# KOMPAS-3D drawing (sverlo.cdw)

Views: Вид 1
Referenced files in D:\Тех\Шестерня\: Сверло.cdw
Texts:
  Сверло спиральное  с коническим хвостовиком @2~28
  Текст на чертеже
  Размерные надписи
  Шероховатость
  Линия-выноска #1
  Линия-выноска #2
  Линия-выноска #3
  Отклонения формы и база
  Заголовок таблицы
  Ячейка таблицы
  Стрелка вида
  Обозначение изменения
  Фигурная скобка
  Номер узла
  Марка координационной оси
  VRCB
  Выносная надпись
  Обозначение узла
  Марка/позиционное обозначение с линией-выноской
  Марка/позиционное обозначение на линии
  Марка/позиционное обозначение без линии-выноски
  Неуказанные предельные отклонения размеров: Н14, h14,  IT14 2 .
  Технические требования по ГОСТ 5756-81
  Rz 20
  Сверло спиральное
  с коническим хвостовиком  28
Dimensions and other numbers on the sheet: 7; 21; 9; 31,6; 8; 24; 124; 12; 25,2; 1,00; 0,07; 130; 280; 118; 25; 0,40; 0,3; 0,15; 16; 24,5; 8 18'; 3,34; 2,19; 20; 0,5; 27,8; 6; 2; 1:1; 1; 0; 3; 4; 5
